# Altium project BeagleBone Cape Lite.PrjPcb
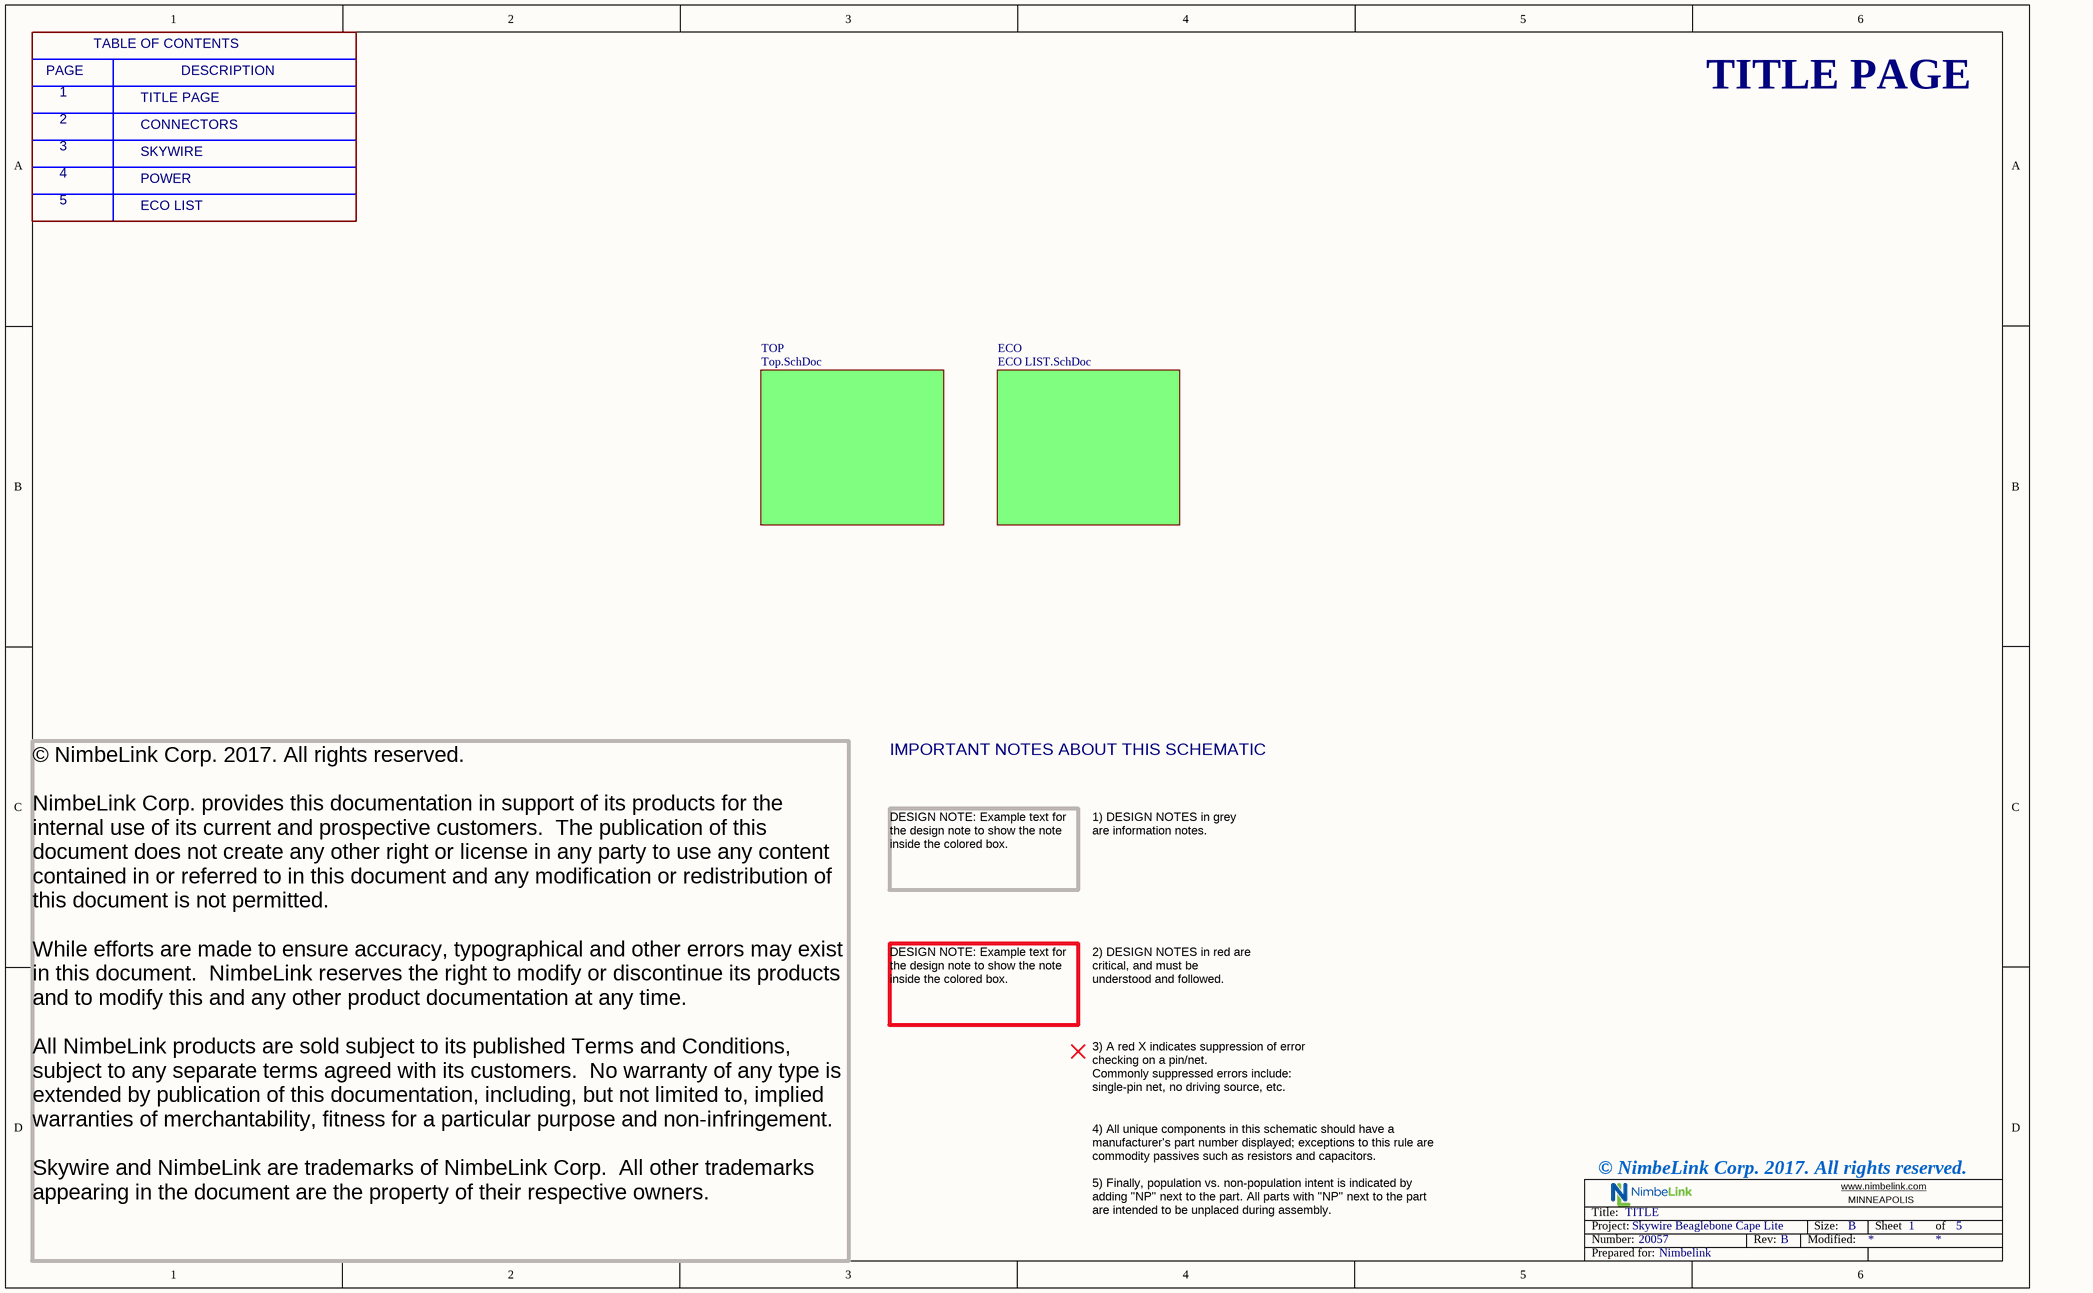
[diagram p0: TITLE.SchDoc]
NL_VERBOSE_CUST_NAME: Nimbelink; NL_SCH_REV: B; NL_SCH_PN: 20057; NL_BILLING_CODE: Skywire Beaglebone Cape Lite
5 sheets, 87 parts. Net scope: flat (ports and power ports of the same name join across sheets).
Board file: 20057.PcbDoc
Sheets:
  TITLE.SchDoc
    TOP = Top.SchDoc
      Skywire = Skywire.SchDoc
      Power = Power.SchDoc
    ECO = ECO LIST.SchDoc

## Sheet TITLE.SchDoc: TITLE
size B; DocumentNumber: 1; SheetNumber: 1; SheetTotal: 5

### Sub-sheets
ECO = ECO LIST.SchDoc: no entries
TOP = Top.SchDoc: no entries

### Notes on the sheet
- PAGE
- 1
- TABLE OF CONTENTS
- TITLE PAGE
- DESCRIPTION
- 2
- 3
- CONNECTORS
- SKYWIRE
- 4
- 5
- ECO LIST
- POWER
- IMPORTANT NOTES ABOUT THIS SCHEMATIC
- DESIGN NOTE: Example text for the design note to show the note inside the colored box.
- 1) DESIGN NOTES in grey are information notes.
- 2) DESIGN NOTES in red are critical, and must be understood and followed.
- 3) A red X indicates suppression of error checking on a pin/net.
  Commonly suppressed errors include: single-pin net, no driving source, etc.
- © NimbeLink Corp. 2017. All rights reserved.
- 4) All unique components in this schematic should have a manufacturer's part number displayed; exceptions to this rule are commodity passives such as resistors and capacitors.
  5) Finally, population vs. non-population intent is indicated by adding "NP" next to the part. All parts with "NP" next to the part are intended to be unplaced during assembly.
- © NimbeLink Corp. 2017. All rights reserved.
  NimbeLink Corp. provides this documentation in support of its products for the internal use of its current and prospective customers.  The publication of this document does not create any other right or license in any party to use any content contained in or referred to in this document and any modification or redistribution of this document is not permitted.
  While efforts are made to ensure accuracy, typographical and other errors may exist in this document.  NimbeLink reserves the right to modify or discontinue its products and to modify this and any other product documentation at any time.
  All NimbeLink products are sold subject to its published Terms and Conditions, subject to any separate terms agreed with its customers.  No warranty of any type is extended by publication of this documentation, including, but not limited to, implied warranties of merchantability, fitness for a particular purpose and non-infringement.
  Skywire and NimbeLink are trademarks of NimbeLink Corp.  All other trademarks appearing in the document are the property of their respective owners.

## Sheet Top.SchDoc: TOP
size B; DocumentNumber: 2; SheetNumber: 2; SheetTotal: 5
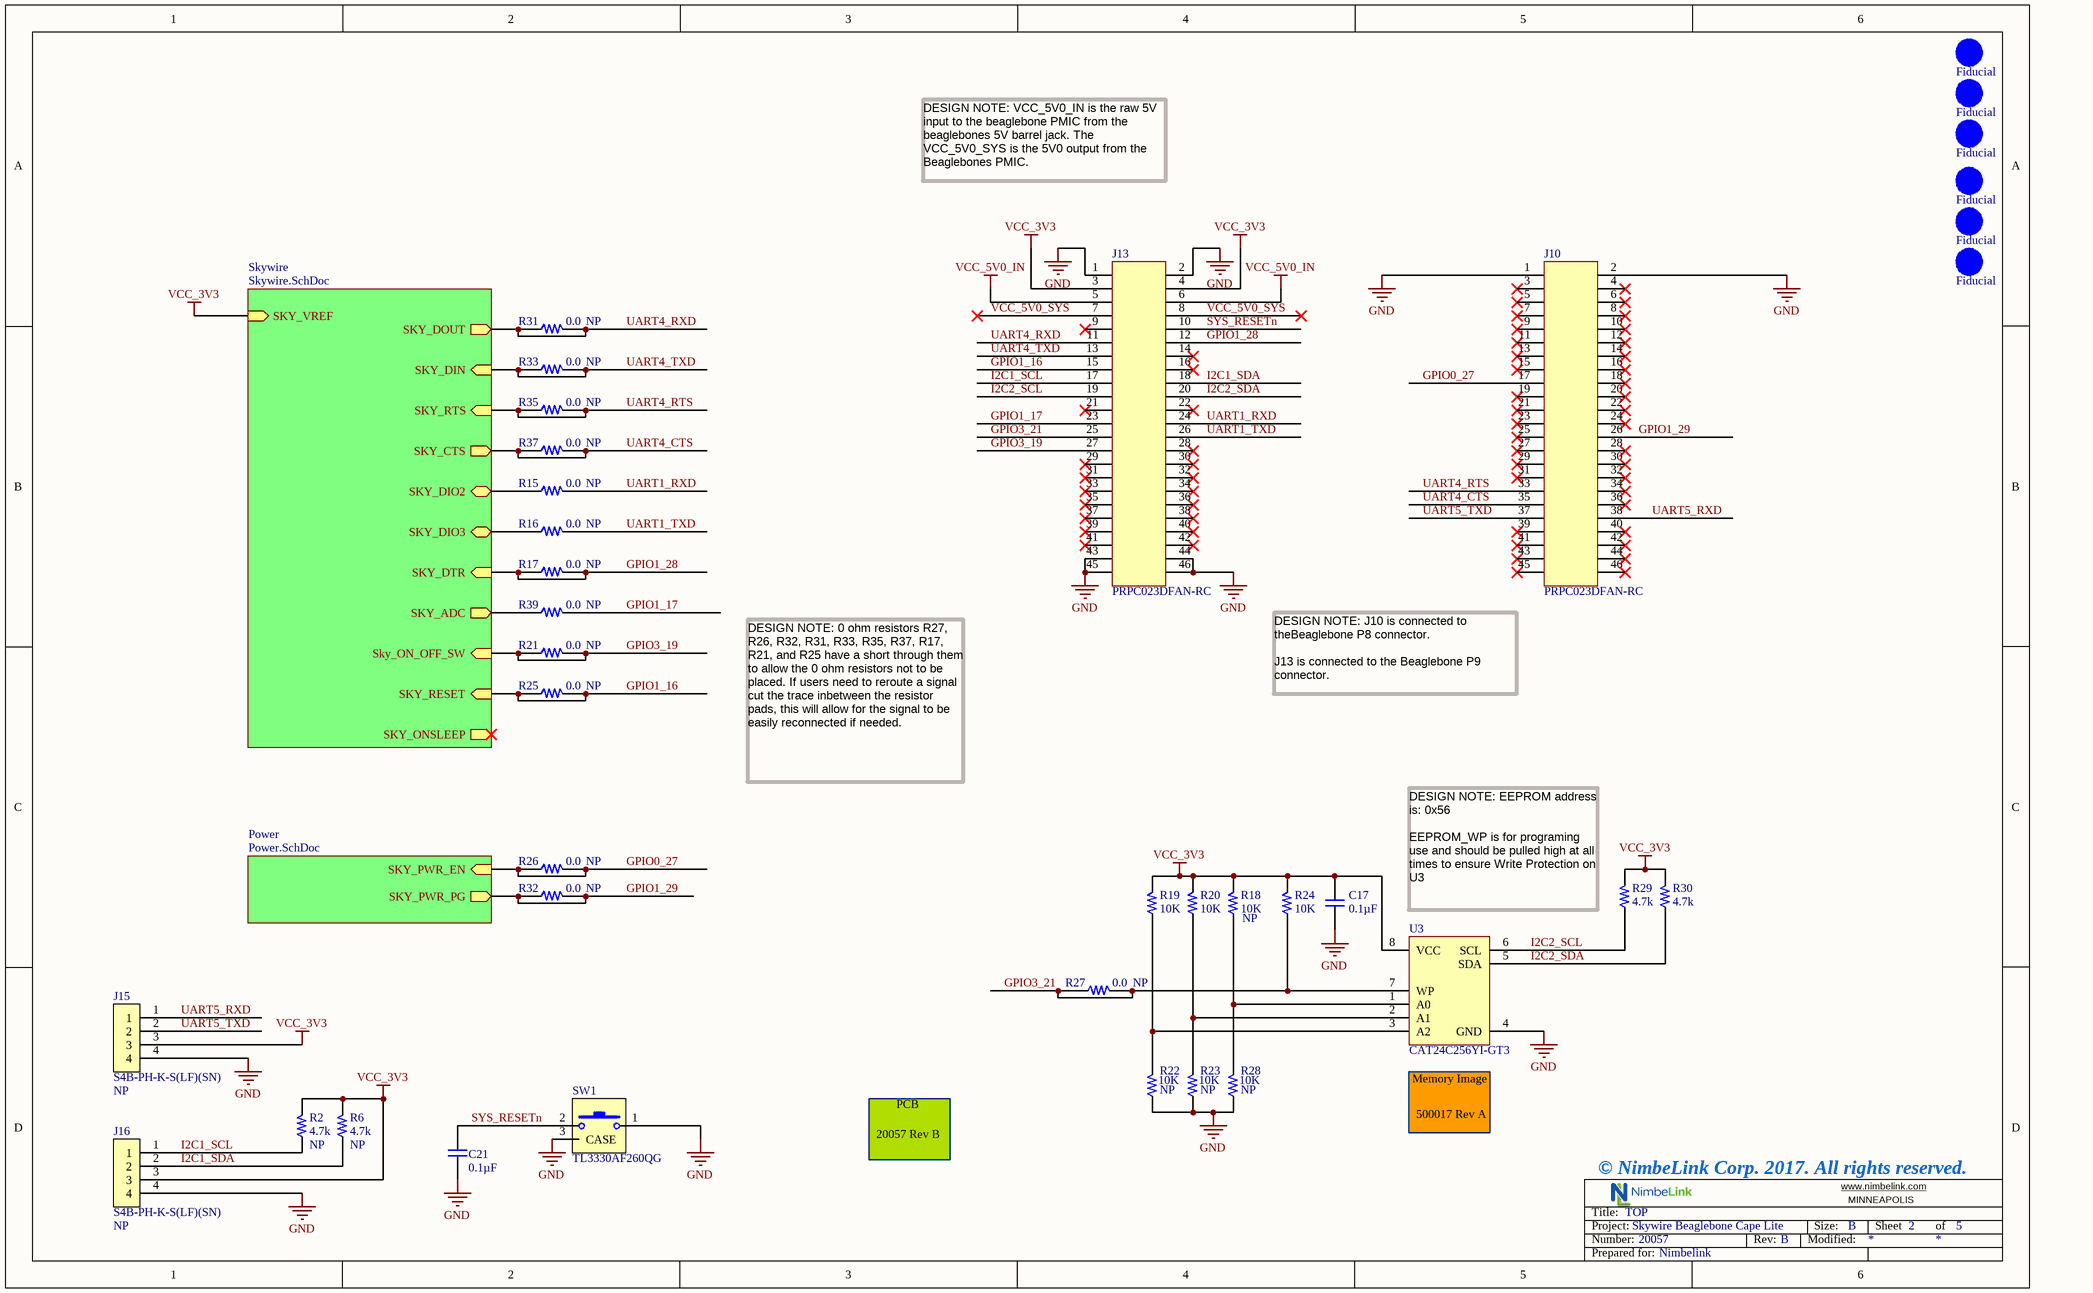
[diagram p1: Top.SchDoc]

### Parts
C17  Capacitance: 0.1µF  [0603]  (hidden comment: C, 0.1 uF, 16V, 5%, X7R, 0603 CER)
C21  Capacitance: 0.1µF  [0603]  (hidden comment: C, 0.1 uF, 16V, 5%, X7R, 0603 CER)
Fiducial1  Fiducial  [Fiducial 1mm]
Fiducial2  Fiducial  [Fiducial 1mm]
Fiducial3  Fiducial  [Fiducial 1mm]
Fiducial4  Fiducial  [Fiducial 1mm]
Fiducial5  Fiducial  [Fiducial 1mm]
Fiducial6  Fiducial  [Fiducial 1mm]
J10  PRPC023DFAN-RC  [PRPC023DFAN-RC]
J13  PRPC023DFAN-RC  [PRPC023DFAN-RC]
J15  Population: NP  [S4B-PH-K-S(LF)(SN)]  (hidden comment: S4B-PH-K-S(LF)(SN))
J16  Population: NP  [S4B-PH-K-S(LF)(SN)]  (hidden comment: S4B-PH-K-S(LF)(SN))
Memory_Image  Manufacturer Part Number 1: 500017 Rev A  (hidden comment: Memory_Image)  (mechanical)
PCB  Manufacturer Part Number 1: 20057 Rev B  (hidden comment: PCB)  (mechanical)
R2  Population: NP  Resistance (Ohms): 4.7k  [0603]  (hidden comment: R, 4.7K, 1%, 1/10W, 0603)
R6  Population: NP  Resistance (Ohms): 4.7k  [0603]  (hidden comment: R, 4.7K, 1%, 1/10W, 0603)
R15  Population: NP  Resistance (Ohms): 0.0  [0603]  (hidden comment: 0)
R16  Population: NP  Resistance (Ohms): 0.0  [0603]  (hidden comment: 0)
R17  Population: NP  Resistance (Ohms): 0.0  [0603]  (hidden comment: 0)
R18  Population: NP  [0603]  (hidden comment: 10K)
R19  10K  [0603]
R20  10K  [0603]
R21  Population: NP  Resistance (Ohms): 0.0  [0603]  (hidden comment: 0)
R22  Population: NP  [0603]  (hidden comment: 10K)
R23  Population: NP  [0603]  (hidden comment: 10K)
R24  10K  [0603]
R25  Population: NP  Resistance (Ohms): 0.0  [0603]  (hidden comment: 0)
R26  Population: NP  Resistance (Ohms): 0.0  [0603]  (hidden comment: 0)
R27  Population: NP  Resistance (Ohms): 0.0  [0603]  (hidden comment: 0)
R28  Population: NP  [0603]  (hidden comment: 10K)
R29  Resistance (Ohms): 4.7k  [0603]  (hidden comment: R, 4.7K, 1%, 1/10W, 0603)
R30  Resistance (Ohms): 4.7k  [0603]  (hidden comment: R, 4.7K, 1%, 1/10W, 0603)
R31  Population: NP  Resistance (Ohms): 0.0  [0603]  (hidden comment: 0)
R32  Population: NP  Resistance (Ohms): 0.0  [0603]  (hidden comment: 0)
R33  Population: NP  Resistance (Ohms): 0.0  [0603]  (hidden comment: 0)
R35  Population: NP  Resistance (Ohms): 0.0  [0603]  (hidden comment: 0)
R37  Population: NP  Resistance (Ohms): 0.0  [0603]  (hidden comment: 0)
R39  Population: NP  Resistance (Ohms): 0.0  [0603]  (hidden comment: 0)
SW1  TL3330AF260QG  [TL3330AF260QG]
U3  CAT24C256YI-GT3  [TSSOP8 4.4x3 CASE 948AL-01]

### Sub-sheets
Power = Power.SchDoc: SKY_PWR_EN (in), SKY_PWR_PG (out)
Skywire = Skywire.SchDoc: SKY_DOUT (out), SKY_DIN (in), SKY_RTS (in), SKY_CTS (out), Sky_ON_OFF_SW (in), SKY_DTR (in), SKY_VREF (in), SKY_DIO2 (bidir), SKY_DIO3 (bidir), SKY_ADC (out), SKY_RESET (in), SKY_ONSLEEP (out)

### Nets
GND: C17.2 C21.2 J10.1 J10.2 J13.1 J13.2 J13.43 J13.44 J13.45 J13.46 J15.4 J16.4 R22.1 R23.1 R28.1 SW1.1 SW1.3(CASE) U3.4(GND)
VCC_3V3: C17.1 J13.3 J13.4 J15.3 J16.3 R2.2 R6.2 R18.2 R19.2 R20.2 R24.2 R29.2 R30.2 U3.8(VCC) ; sheet Skywire/SKY_VREF
VCC_5V0_IN: J13.5 J13.6
GPIO0_27: J10.17 R26.1 R26.2 ; sheet Power/SKY_PWR_EN
GPIO1_16: J13.15 R25.1 R25.2 ; sheet Skywire/SKY_RESET
GPIO1_17: J13.23 R39.2
GPIO1_28: J13.12 R17.1 R17.2 ; sheet Skywire/SKY_DTR
GPIO1_29: J10.26 R32.1 R32.2 ; sheet Power/SKY_PWR_PG
GPIO3_19: J13.27 R21.1 R21.2 ; sheet Skywire/Sky_ON_OFF_SW
GPIO3_21: J13.25 R24.1 R27.1 R27.2 U3.7(WP)
I2C1_SCL: J13.17 J16.1 R2.1
I2C1_SDA: J13.18 J16.2 R6.1
I2C2_SCL: J13.19 R29.1 U3.6(SCL)
I2C2_SDA: J13.20 R30.1 U3.5(SDA)
SYS_RESETn: C21.1 J13.10 SW1.2
UART1_RXD: J13.24 R15.2
UART1_TXD: J13.26 R16.2
UART4_CTS: J10.35 R37.1 R37.2 ; sheet Skywire/SKY_CTS
UART4_RTS: J10.33 R35.1 R35.2 ; sheet Skywire/SKY_RTS
UART4_RXD: J13.11 R31.1 R31.2 ; sheet Skywire/SKY_DOUT
UART4_TXD: J13.13 R33.1 R33.2 ; sheet Skywire/SKY_DIN
UART5_RXD: J10.38 J15.1
UART5_TXD: J10.37 J15.2
VCC_5V0_SYS: J13.7 J13.8
NetR15_1: R15.1 ; sheet Skywire/SKY_DIO2
NetR16_1: R16.1 ; sheet Skywire/SKY_DIO3
NetR18_1: R18.1 R28.2 U3.1(A0)
NetR19_1: R19.1 R22.2 U3.3(A2)
NetR20_1: R20.1 R23.2 U3.2(A1)
NetR39_1: R39.1 ; sheet Skywire/SKY_ADC

Not connected (* = marked no-connect by the designer): J10 3* 4* 5* 6* 7* 8* 9* 10* 11* 12* 13* 14* 15* 16* 18* 19* 20* 21* 22* 23* 24* 25* 27* 28* 29* 30* 31* 32* 34* 36* 39* 40* 41* 42* 43* 44* 45* 46*; J13 9* 14* 16* 21* 22* 28* 29* 30* 31* 32* 33* 34* 35* 36* 37* 38* 39* 40* 41* 42*

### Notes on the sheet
- DESIGN NOTE: VCC_5V0_IN is the raw 5V input to the beaglebone PMIC from the beaglebones 5V barrel jack. The VCC_5V0_SYS is the 5V0 output from the Beaglebones PMIC.
- (near J10) DESIGN NOTE: J10 is connected to theBeaglebone P8 connector.
  J13 is connected to the Beaglebone P9 connector.
- DESIGN NOTE: 0 ohm resistors R27, R26, R32, R31, R33, R35, R37, R17, R21, and R25 have a short through them to allow the 0 ohm resistors not to be placed. If users need to reroute a signal cut the trace inbetween the resistor pads, this will allow for the signal to be easily reconnected if needed.
- DESIGN NOTE: EEPROM address is: 0x56
  EEPROM_WP is for programing use and should be pulled high at all times to ensure Write Protection on U3
- © NimbeLink Corp. 2017. All rights reserved.

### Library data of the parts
C17 C21 = C, 0.1 uF, 16V, 5%, X7R, 0603 CER: Manufacturer: Samsung Electro-Mechanics America, Inc.; Manufacturer Part Number: CL10B104JO8NNNC
Fiducial1-Fiducial6 = Fiducial: Fiducial, 1mm; Population: NP
J10 J13 = PRPC023DFAN-RC: J, HEADER, MALE, 2.54mm, 23x2, 8.08mm,TH; Manufacturer 1: Sullins Connector Solutions; Connector Type: Header, Breakaway; Pitch - Mating: 0.100" (2.54mm); Shrouding: Unshrouded; Number of Positions: 46; Number of Positions Loaded: All; Contact Length - Mating: 0.318" (8.08mm)
J15 J16 = S4B-PH-K-S(LF)(SN): J, HEADER, MALE, RA, 2.00mm, 4x1, TH; Manufacturer: JST Sales America Inc.; Connector Type: Header, Shrouded; Number of Positions: 4; Number of Positions Loaded: All; Pitch: 0.079" (2.00mm)
Memory_Image = Memory_Image: Memory Image; Manufacturer 1: Nimbelink
PCB = PCB: PCB Part Number; Manufacturer 1: Nimbelink
R2 R6 R29 R30 = R, 4.7K, 1%, 1/10W, 0603: Manufacturer: Samsung Electro-Mechanics America, Inc; Manufacturer Part Number: RC1608F472CS; Power (Watts): 0.1W, 1/10W; Temperature Coefficient: ±100ppm/°C
R15-R17 R21 R25-R27 R31-R33 R35 R37 R39 = R, 0, 1/10W, 0603: Manufacturer: Panasonic Electronic Components; Manufacturer Part Number: ERJ-3GEY0R00V; Tolerance: Jumper; Power (Watts): 0.1W, 1/10W
R18-R20 R22-R24 R28 = R, 10K, 1%, 1/10W, 0603: Power Rating: 100 mW; Temperature Coefficient: 100 PPM / C; Voltage Rating: 75 V; Brand: Panasonic; Case Height: 0.45 mm; Case Length: 1.6 mm; Case Width: 0.8 mm
SW1 = TL3330AF260QG: SW, SPST-NO, 12V, 0.05A, 6.90x3.40mm, SMD, RIGHT ANGLE; Manufacturer: E-Switch; Switch Function: Off-Mom; Contact Rating @ Voltage: 0.05A @ 12VDC; Actuator Type: Rectangular Button; Actuator Height off PCB, from Pins: 3.50mm; Actuator Orientation: Side Actuated; Outline: 6.90mm x 3.40mm; Illumination: Non-Illuminated; Operating Force: 260gf; Actuator Material: Polyamide (PA), Nylon; Switch Travel: 0.25mm; Mechanical Life: 30,000 Cycles
U3 = CAT24C256YI-GT3: U, EEPROM, I2C, 256KB, 400kHz, 1.8V-5.5V, TSSOP8; Manufacturer 1: ON Semiconductor; Format - Memory: EEPROMs - Serial; Memory Size: 256K (32K x 8); Interface: I²C, 2-Wire Serial; Voltage - Supply: 1.8 V ~ 5.5 V

## Sheet Skywire.SchDoc: SKYWIRE
size B; DocumentNumber: 3; SheetNumber: 3; SheetTotal: 5
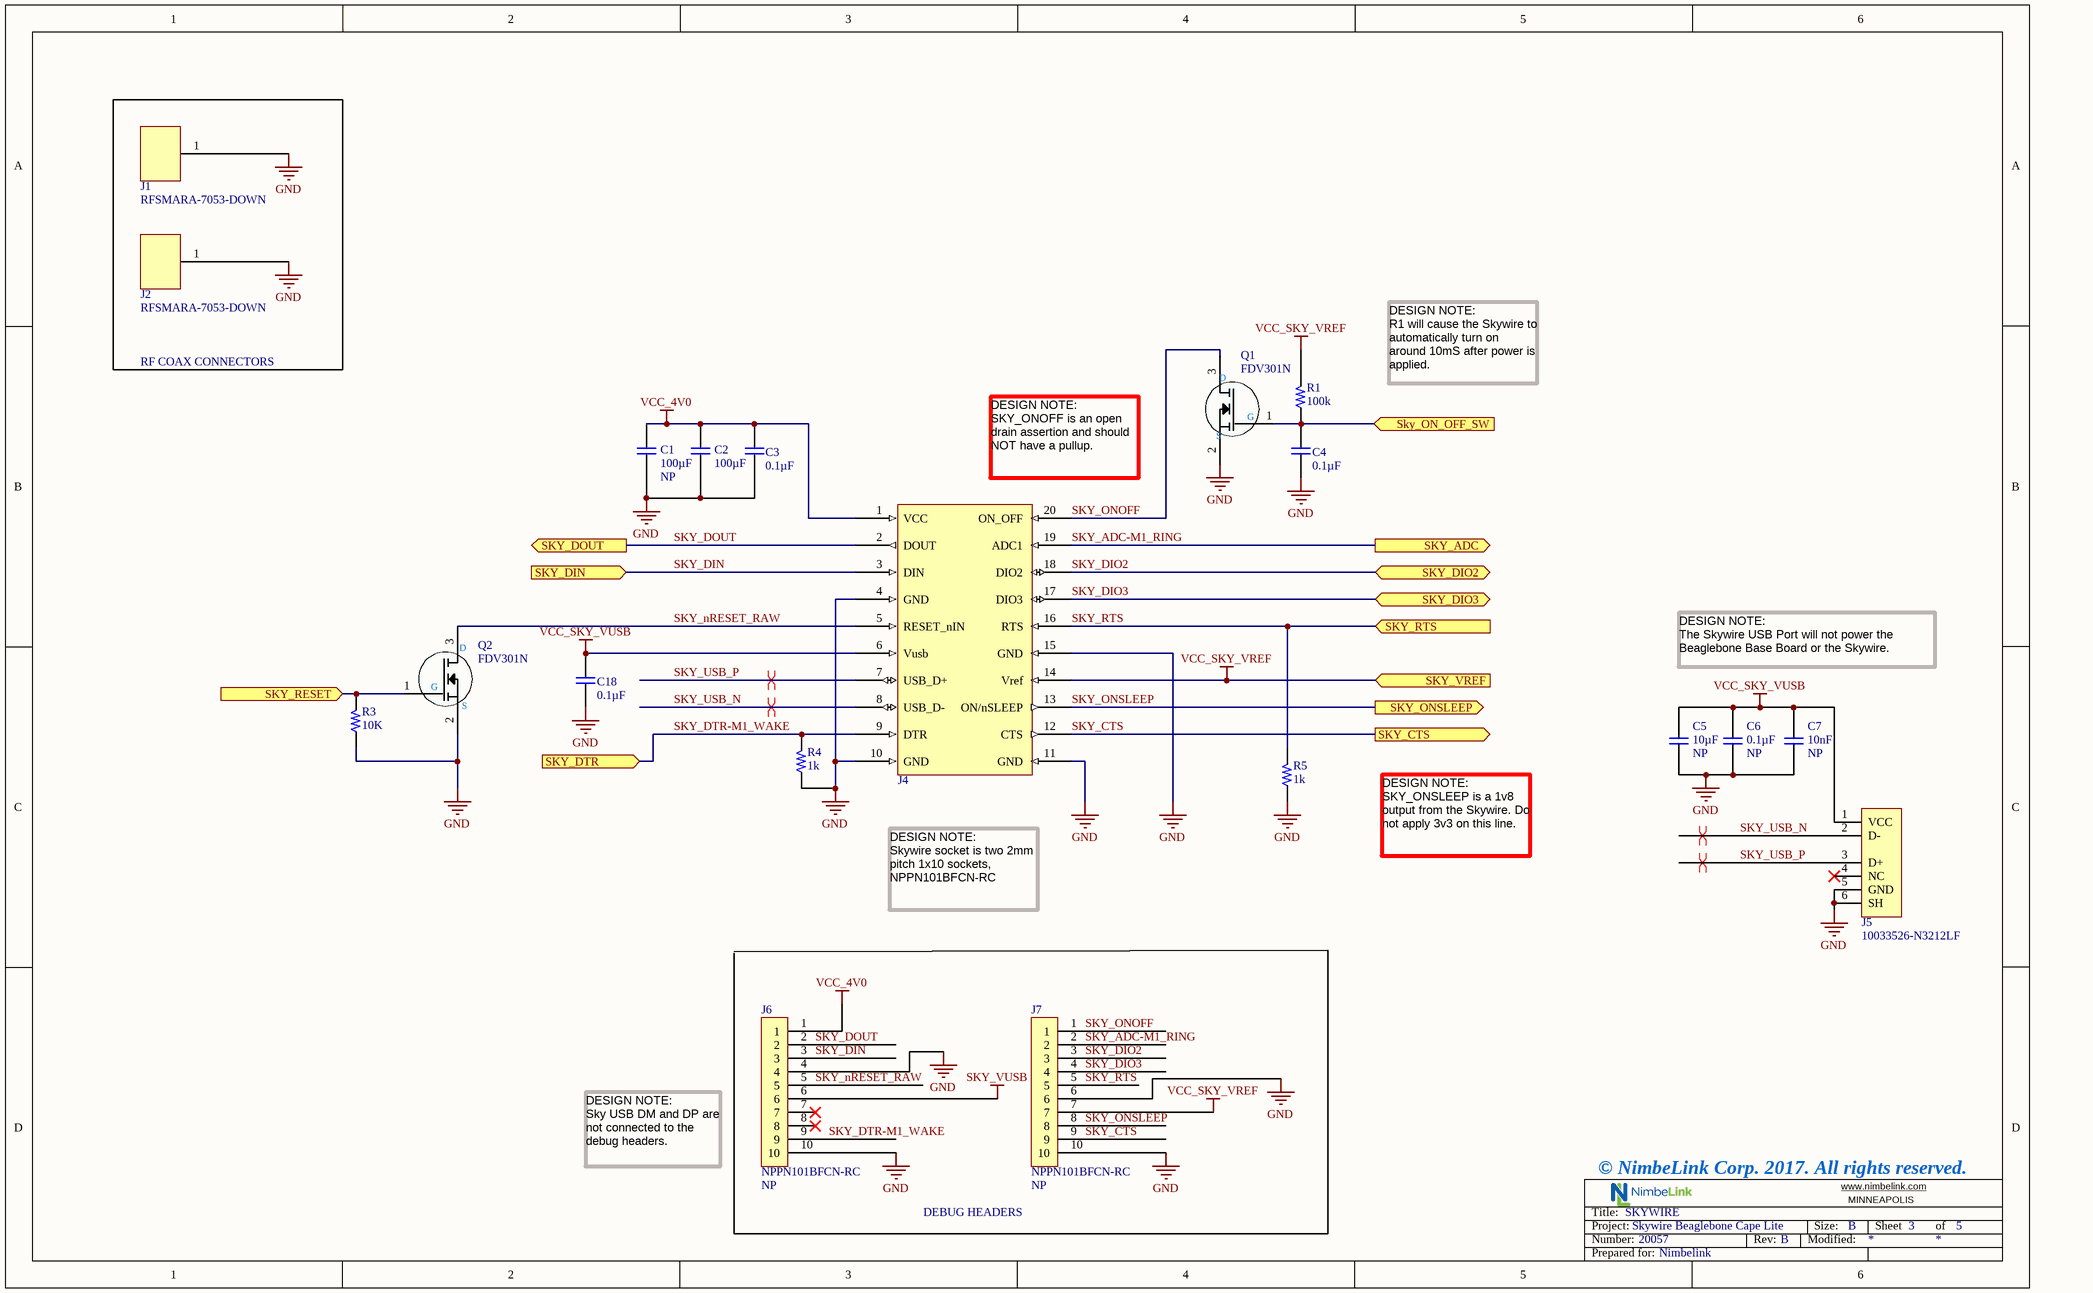
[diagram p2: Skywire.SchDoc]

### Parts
C1  Population: NP  Capacitance: 100µF  [CAPC3225X25N_1210]  (hidden comment: LMK325BJ107MM-T)
C2  Capacitance: 100µF  [CAPC3225X25N_1210]  (hidden comment: LMK325BJ107MM-T)
C3  Capacitance: 0.1µF  [0603]  (hidden comment: C, 0.1 uF, 16V, 5%, X7R, 0603 CER)
C4  Capacitance: 0.1µF  [0603]  (hidden comment: C, 0.1 uF, 16V, 5%, X7R, 0603 CER)
C5  Capacitance: 10µF  Population: NP  [0805]  (hidden comment: C, 10 uF, 25V, 10% ,X5R, 0805 CER)
C6  Population: NP  Capacitance: 0.1µF  [0603]  (hidden comment: C, 0.1 uF, 16V, 5%, X7R, 0603 CER)
C7  Population: NP  Capacitance: 10nF  [0603]  (hidden comment: C, 10 nF, 25V, 10%, X7R, 0603 CER)
C18  Capacitance: 0.1µF  [0603]  (hidden comment: C, 0.1 uF, 16V, 5%, X7R, 0603 CER)
J1  UFL to SMA  [UFL TO SMA]  (value not drawn)
J2  UFL to SMA  [UFL TO SMA]  (value not drawn)
J4  SKYWIRE SOCKET TH  [SKYWIRE SOCKET]  (value not drawn)
J5  USB MINI B  [10033526-N3212LF]  (value not drawn)
J6  Population: NP  [Socket 2mm 1x10 NP]  (hidden comment: NPPN101BFCN-RC)
J7  Population: NP  [Socket 2mm 1x10 NP]  (hidden comment: NPPN101BFCN-RC)
Q1  FDV301N  [SOT95P300X115-3N]
Q2  FDV301N  [SOT95P300X115-3N]
R1  100K  [0603]
R3  10K  [0603]
R4  1k  [0603]
R5  1k  [0603]

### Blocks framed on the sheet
RF COAX CONNECTORS: J1 J2
DEBUG HEADERS: J6 J7

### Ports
SKY_ADC (out), SKY_CTS (out), SKY_DIN (in), SKY_DIO2 (bidir), SKY_DIO3 (bidir), SKY_DOUT (out), SKY_DTR (in), Sky_ON_OFF_SW (in), SKY_ONSLEEP (out), SKY_RESET (in), SKY_RTS (in), SKY_VREF (in)

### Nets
GND: C1.2 C2.2 C3.2 C4.2 C5.2 C6.2 C7.2 C18.2 J1.1 J2.1 J4.4(GND) J4.10(GND) J4.11(GND) J4.15(GND) J5.5(GND) J5.6(SH) J6.4 J6.10 J7.6 J7.10 Q1.2(S) Q2.2(S) R3.1 R4.1 R5.1
SKY_VUSB: J6.6
VCC_4V0: C1.1 C2.1 C3.1 J4.1(VCC) J6.1
VCC_SKY_VREF: J4.14(Vref) J7.7 R1.2 ; port SKY_VREF
VCC_SKY_VUSB: C5.1 C6.1 C7.1 C18.1 J4.6(Vusb) J5.1(VCC)
SKY_ADC-M1_RING: J4.19(ADC1) J7.2 ; port SKY_ADC
SKY_CTS: J4.12(CTS) J7.9 ; port SKY_CTS
SKY_DIN: J4.3(DIN) J6.3 ; port SKY_DIN
SKY_DIO2: J4.18(DIO2) J7.3 ; port SKY_DIO2
SKY_DIO3: J4.17(DIO3) J7.4 ; port SKY_DIO3
SKY_DOUT: J4.2(DOUT) J6.2 ; port SKY_DOUT
SKY_DTR-M1_WAKE: J4.9(DTR) J6.9 R4.2 ; port SKY_DTR
SKY_nRESET_RAW: J4.5(RESET_nIN) J6.5 Q2.3(D)
SKY_ONOFF: J4.20(ON_OFF) J7.1 Q1.3(D)
SKY_ONSLEEP: J4.13(ON/nSLEEP) J7.8 ; port SKY_ONSLEEP
SKY_RTS: J4.16(RTS) J7.5 R5.2 ; port SKY_RTS
SKY_USB_N: J4.8(USB_D-) J5.2(D-)
SKY_USB_P: J4.7(USB_D+) J5.3(D+)
NetC4_1: C4.1 Q1.1(G) R1.1 ; port Sky_ON_OFF_SW
NetQ2_1: Q2.1(G) R3.2 ; port SKY_RESET

Not connected (* = marked no-connect by the designer): J5 4(NC)*; J6 7* 8*

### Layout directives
differential pair: SKY_USB_N, SKY_USB_P
differential pair; net class DIFF90: SKY_USB_N, SKY_USB_P

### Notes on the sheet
- DESIGN NOTE:
  R1 will cause the Skywire to automatically turn on around 10mS after power is applied.
- (near J4) DESIGN NOTE:
  SKY_ONOFF is an open drain assertion and should NOT have a pullup.
- DESIGN NOTE:
  The Skywire USB Port will not power the Beaglebone Base Board or the Skywire.
- DESIGN NOTE:
  Skywire socket is two 2mm pitch 1x10 sockets, NPPN101BFCN-RC
- DESIGN NOTE:
  SKY_ONSLEEP is a 1v8 output from the Skywire. Do not apply 3v3 on this line.
- DESIGN NOTE:
  Sky USB DM and DP are not connected to the debug headers.
- © NimbeLink Corp. 2017. All rights reserved.

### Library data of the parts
C1 C2 = LMK325BJ107MM-T: C, 100 uF, 10V, 20%, X5R, 1210 CER; Manufacturer 1: Taiyo Yuden
C3 C4 C6 C18 = C, 0.1 uF, 16V, 5%, X7R, 0603 CER: as C17 on sheet Top
C5 = C, 10 uF, 25V, 10% ,X5R, 0805 CER: Manufacturer: Samsung Electro-Mechanics America, Inc; Manufacturer Part Number: CL21A106KAYNNNE
C7 = C, 10 nF, 25V, 10%, X7R, 0603 CER: Manufacturer: TDK Corporation; Manufacturer Part Number: C1608X7R1E103K080AA
J1 J2 = RFSMARA-7053-DOWN: J, ANT, UFL to SMA, TH; Manufacturer Contact Name: Anna Xiao; Manufacturer Email: anna@rohoconnector.com; Manufacturer 1: ROHO CONNECTOR
J4 = SKYWIRE SOCKET TH: J, Cellular, Nimbelink, Skywire, 3.6V-4.2V, Through Hole XBEE; Manufacturer: Sullins Connector Solutions; Manufacturer Part Number: NPPN101BFCN-RC; Connector Type: Header; Number of Positions: 10; Number of Positions Loaded: All; Pitch: 0.079" (2.00mm)
J5 = 10033526-N3212LF: J, USB, MINI B, RIGHT ANGLE, SMD; Manufacturer: Amphenol FCI; Connector Type: USB - mini B; Number of Contacts: 5; Gender: Receptacle
J6 J7 = NPPN101BFCN-RC: J, HEADER, FEMALE, 2.00mm, 10x1, TH; Manufacturer: Sullins Connector Solutions; Number of Positions: 10; Number of Positions Loaded: All; Pitch: 0.079" (2.00mm)
Q1 Q2 = FDV301N: Q, MOSFET, N-CH, 25V, 0.220mA, SOT-23-3; Configuration: Single; Brand: Fairchild Semiconductor; Forward Transconductance - Min: 0.2 S; Transistor Polarity: N-Channel; Channel Mode: Enhancement; Fall Time: 6 ns; Id - Continuous Drain Current: 220 mA; Pd - Power Dissipation: 0.35 W; Rds On - Drain-Source Resistance: 5 Ohms; Typical Turn-Off Delay Time: 3.5 ns; Vgs - Gate-Source Breakdown Voltage: 8 V
R1 = R, 100K, 1%, 1/10W, 0603: Manufacturer 1: Samsung Electro-Mechanics America, Inc; Manufacturer Part Number 1: RC1608F104CS; Power (Watts): 0.1W, 1/10W; Temperature Coefficient: ±100ppm/°C
R3 = R, 10K, 1%, 1/10W, 0603: as R18 on sheet Top
R4 R5 = R, 1K, 1%, 1/10W, 0603: Manufacturer: Panasonic Electronic Components; Manufacturer Part Number: ERJ-3EKF1001V; Power (Watts): 0.1W, 1/10W; Temperature Coefficient: ±100ppm/°C

## Sheet Power.SchDoc: POWER
size B; DocumentNumber: 4; SheetNumber: 4; SheetTotal: 5
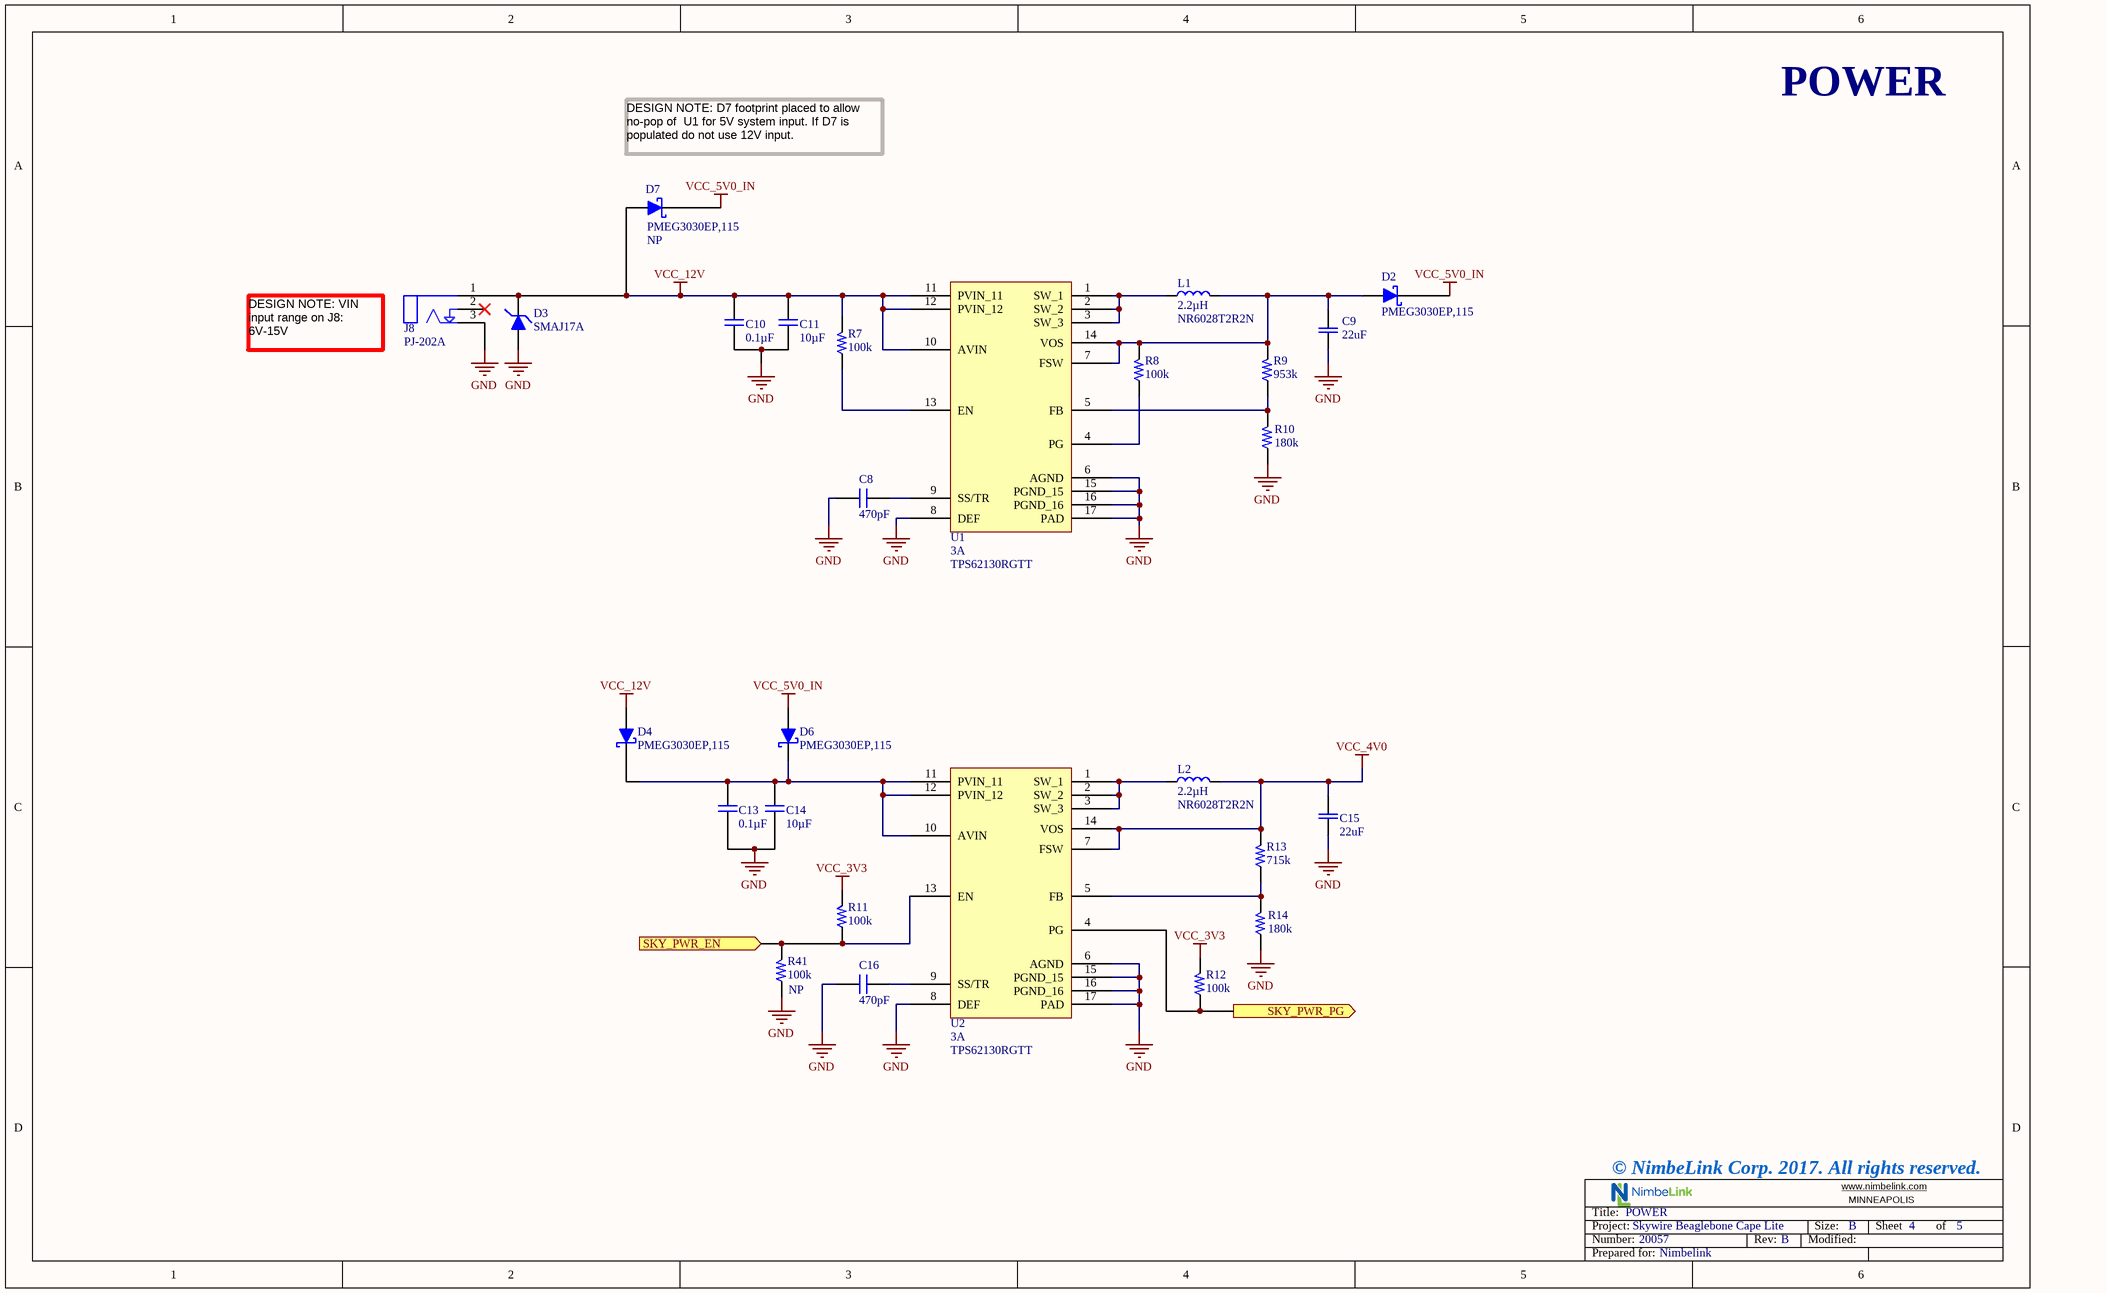
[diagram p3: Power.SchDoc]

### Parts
C8  Capacitance: 470pF  [0603]  (hidden comment: C, 470 pF, 50V, NP0, 0603 CER_1)
C9  22uF  [0805]
C10  Capacitance: 0.1µF  [0603]  (hidden comment: C, 0.1 uF, 16V, 5%, X7R, 0603 CER)
C11  Capacitance: 10µF  [0805]  (hidden comment: C, 10 uF, 25V, 10% ,X5R, 0805 CER)
C13  Capacitance: 0.1µF  [0603]  (hidden comment: C, 0.1 uF, 16V, 5%, X7R, 0603 CER)
C14  Capacitance: 10µF  [0805]  (hidden comment: C, 10 uF, 25V, 10% ,X5R, 0805 CER)
C15  22uF  [0805]
C16  Capacitance: 470pF  [0603]  (hidden comment: C, 470 pF, 50V, NP0, 0603 CER_1)
D2  PMEG3030EP,115  [SOD128]
D3  SMAJ17A  [DO-214AC, SMA]
D4  PMEG3030EP,115  [SOD128]
D6  PMEG3030EP,115  [SOD128]
D7  Population: NP  [SOD128]  (hidden comment: PMEG3030EP,115)
J8  PJ-202A  [PJ-202A]
L1  Inductance: 2.2µH  [NR6028]  (hidden comment: NR6028T2R2N)
L2  Inductance: 2.2µH  [NR6028]  (hidden comment: NR6028T2R2N)
R7  100K  [0603]
R8  100K  [0603]
R9  Resistance (Ohms): 953k  [0603]  (hidden comment: R, 953K, 1%, 1/10W, 0603)
R10  Resistance (Ohms): 180k  [0603]  (hidden comment: R, 180K, 1%, 1/10W, 0603)
R11  100K  [0603]
R12  100K  [0603]
R13  715K  [0603]
R14  Resistance (Ohms): 180k  [0603]  (hidden comment: R, 180K, 1%, 1/10W, 0603)
R41  Population: NP  [0603]  (hidden comment: 100K)
U1  Current - Output: 3A  Manufacturer Part Number: TPS62130RGTT  [QFN50P300X300X100_HS-17N]  (hidden comment: TPS62130)
U2  Current - Output: 3A  Manufacturer Part Number: TPS62130RGTT  [QFN50P300X300X100_HS-17N]  (hidden comment: TPS62130)

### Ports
SKY_PWR_EN (in), SKY_PWR_PG (out)

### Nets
GND: C8.1 C9.2 C10.2 C11.2 C13.2 C14.2 C15.2 C16.1 D3.A J8.3 R10.1 R14.1 R41.1 U1.6(AGND) U1.8(DEF) U1.15(PGND_15) U1.16(PGND_16) U1.17(PAD) U2.6(AGND) U2.8(DEF) U2.15(PGND_15) U2.16(PGND_16) U2.17(PAD)
VCC_3V3: R11.2 R12.2
VCC_4V0: C15.1 L2.2 R13.2 U2.7(FSW) U2.14(VOS)
VCC_5V0_IN: D2.K D6.A D7.K
VCC_12V: C10.1 C11.1 D3.K D4.A D7.A J8.1 R7.2 U1.10(AVIN) U1.11(PVIN_11) U1.12(PVIN_12)
NetC8_2: C8.2 U1.9(SS/TR)
NetC9_1: C9.1 D2.A L1.2 R8.2 R9.2 U1.7(FSW) U1.14(VOS)
NetC13_1: C13.1 C14.1 D4.K D6.K U2.10(AVIN) U2.11(PVIN_11) U2.12(PVIN_12)
NetC16_2: C16.2 U2.9(SS/TR)
NetL1_1: L1.1 U1.1(SW_1) U1.2(SW_2) U1.3(SW_3)
NetL2_1: L2.1 U2.1(SW_1) U2.2(SW_2) U2.3(SW_3)
NetR7_1: R7.1 U1.13(EN)
NetR8_1: R8.1 U1.4(PG)
NetR9_1: R9.1 R10.2 U1.5(FB)
NetR11_1: R11.1 R41.2 U2.13(EN) ; port SKY_PWR_EN
NetR12_1: R12.1 U2.4(PG) ; port SKY_PWR_PG
NetR13_1: R13.1 R14.2 U2.5(FB)

Not connected (* = marked no-connect by the designer): J8 2*

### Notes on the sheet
- POWER
- DESIGN NOTE: D7 footprint placed to allow no-pop of  U1 for 5V system input. If D7 is populated do not use 12V input.
- DESIGN NOTE: VIN input range on J8: 6V-15V
- © NimbeLink Corp. 2017. All rights reserved.

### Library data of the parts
C8 C16 = C, 470 pF, 50V, NP0, 0603 CER_1: C, 470 pF, 50V, NP0, 0603 CER; Manufacturer: Samsung Electro-Mechanics America, Inc; Manufacturer Part Number: CL10C471JB8NCNC; Tolerance: ±5%; Temperature Coefficient: C0G, NP0
C9 C15 = CAP 22uF 10V 20% X5R 0805 CER: Manufacturer 1: Samsung Electro-Mechanics America, Inc; Manufacturer Part Number 1: CL21A226MPQNNNE; Capacitance: 22µF
C10 C13 = C, 0.1 uF, 16V, 5%, X7R, 0603 CER: as C17 on sheet Top
C11 C14 = C, 10 uF, 25V, 10% ,X5R, 0805 CER: as C5 on sheet Skywire
D2 D4 D6 D7 = PMEG3030EP,115: D, SCHOTTKY, 30V, 0.360VF, 3A, SOD-128; Manufacturer 1: NXP USA Inc.; Voltage - Forward (Vf) (Max) @ If: 360mV @ 3A; Speed: Fast Recovery =< 500ns, > 200mA (Io); Current - Reverse Leakage @ Vr: 5mA @ 30V; Capacitance @ Vr, F: 470pF @ 1V, 1MHz
D3 = SMAJ17A: D, TVS, UNIDIRECTIONAL, 17V, 14.5A, SMA; Manufacturer: Bourns Inc.; Type: Zener; Unidirectional Channels: 1; Voltage - Breakdown (Min): 18.9V; Voltage - Clamping (Max) @ Ipp: 27.6V; Power - Peak Pulse: 400W; Power Line Protection: No
J8 = PJ-202A: J, Barrel, 2.1mm ID, 5.5mm OD; Manufacturer 1: CUI Inc; Connector Type: Jack; Gender: Male; Number of Positions/Contacts: 2 Conductors, 3 Contacts; Internal Switch(s): Single Switch, Normally Closed; Shielding: Unshielded; Voltage - Rated: 16VDC; Current Rating: 2.5A
L1 L2 = NR6028T2R2N: L, 2.2uH, 3.7A, 26 mOHM, 30%, 6x6x2.8mm; Manufacturer 1: Taiyo Yuden; Type: Wirewound; Material - Core: Ferrite; Current - Saturation: 4.2A; Shielding: Shielded; DC Resistance (DCR): 26 mOhm Max; Frequency - Self Resonant: 68MHz; Frequency - Test: 100kHz
R7 R8 R11 R12 R41 = R, 100K, 1%, 1/10W, 0603: as R1 on sheet Skywire
R9 = R, 953K, 1%, 1/10W, 0603: Manufacturer 1: Panasonic Electronic Components; Manufacturer Part Number 1: ERJ-3EKF9533V; Power (Watts): 0.1W, 1/10W; Temperature Coefficient: ±100ppm/°C
R10 R14 = R, 180K, 1%, 1/10W, 0603: Manufacturer: Yageo; Manufacturer Part Number: RC0603FR-07180KL; Power (Watts): 0.1W, 1/10W; Temperature Coefficient: ±100ppm/°C
R13 = R, 715K, 1%, .1W, 0603: Manufacturer: Panasonic Electronic Components; Manufacturer Part Number: ERJ-3EKF7153V; Power (Watts): 0.1W, 1/10W; Temperature Coefficient: ±100ppm/°C
U1 U2 = TPS62130: U, DC/DC BUCK, 3V-17V , 3A, QFN; Manufacturer: Texas Instruments; Output Type: Adjustable; Number of Outputs: 1; Voltage - Output: 0.9 V ~ 6 V; Voltage - Input: 3 V ~ 17 V; Frequency - Switching: 2.5MHz; Synchronous Rectifier: Yes

## Sheet ECO LIST.SchDoc: ECO LIST
size C; DocumentNumber: 5; SheetNumber: 5; SheetTotal: 5
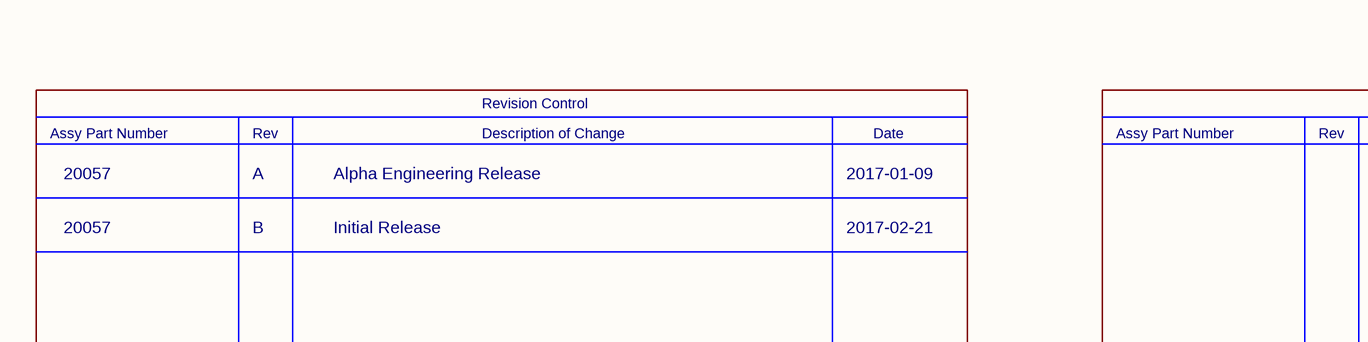
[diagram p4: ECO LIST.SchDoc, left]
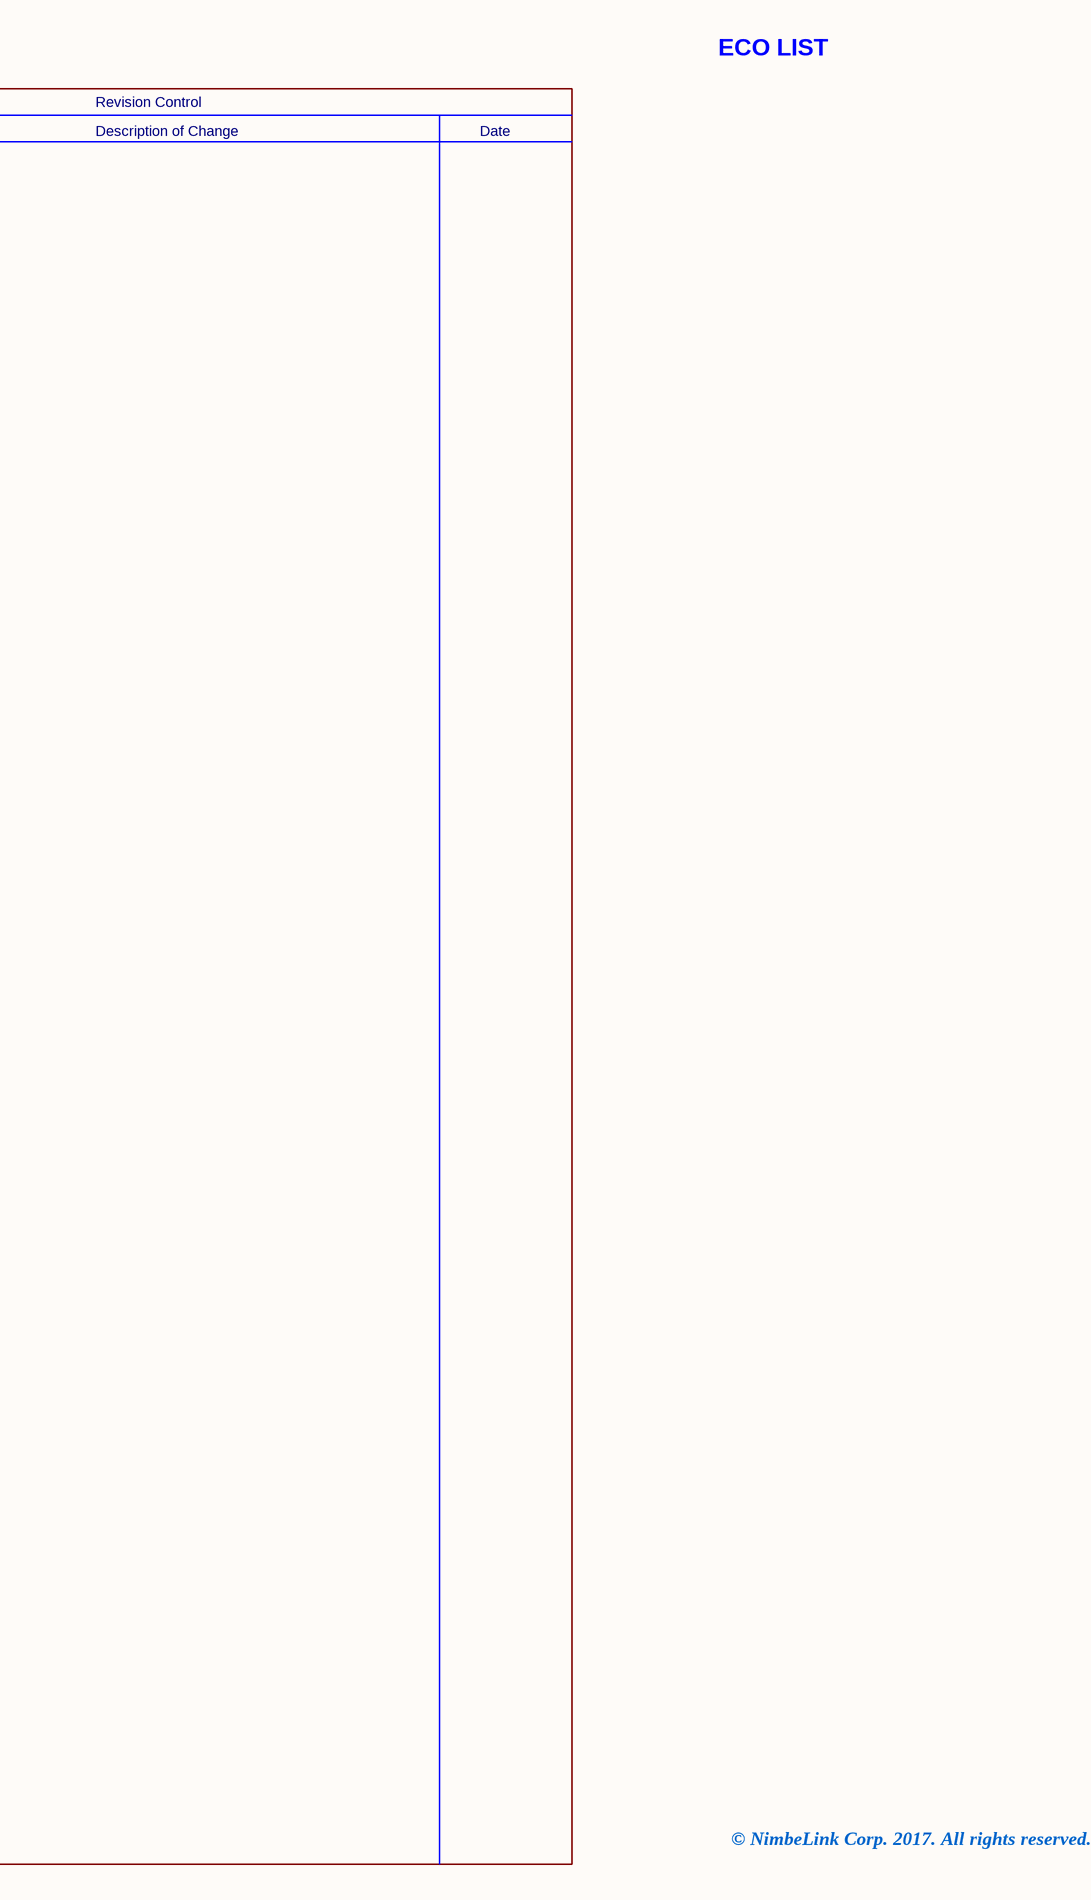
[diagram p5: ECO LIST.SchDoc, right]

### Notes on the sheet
- ECO LIST
- Assy Part Number
- Rev
- Description of Change
- Revision Control
- Date
- 20057
- A
- Alpha Engineering Release
- 2017-01-09
- B
- Initial Release
- 2017-02-21
- © NimbeLink Corp. 2017. All rights reserved.

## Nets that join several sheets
GND: Top (18 pins), Skywire (25 pins), Power (23 pins)
VCC_3V3: Top (14 pins), Power (R11.2 R12.2)
VCC_4V0: Skywire (5 pins), Power (5 pins)
VCC_5V0_IN: Top (J13.5 J13.6), Power (D2.K D6.A D7.K)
